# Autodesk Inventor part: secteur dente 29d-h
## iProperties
Author: chr
Shininess: 20.0
Angle Display Precision: 2
Document Length Units: 11269
Document Angle Units: 11283
Document Time Units: 11279
Document Mass Units: 11290
Document Length Units Precision: 3
Document Angle Units Precision: 2
Compacted: False
PropertySet Name: _Private Model Information
Created: 2002-03
Part Number: secteur dente 29d-h
Material: Par défaut
Document SubType Name: Modélisation
Designer: chr
Control State: 0
Master: False
Checked Out: False
PropertySet Name: Design Tracking Control
Density: 0.0
Volumn: 0.0
Area: 0.0
PropertySet Name: Model Information
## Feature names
1. Base1
2. Extrusion1
3. Extrusion2
4. Réseau circulaire1 [Circular Pattern]
